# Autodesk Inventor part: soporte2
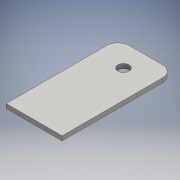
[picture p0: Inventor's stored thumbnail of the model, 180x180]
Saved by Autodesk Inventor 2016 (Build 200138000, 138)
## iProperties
Created: 2016-06
Part Number: soporte2
Material: Genérico
Document SubType Name: Modeling
Designer: adm
Density: 1 g/cm^3
Appearance: Valor por defecto
Author: adm
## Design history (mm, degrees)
sketch "Boceto1"
  geometry: L1 (-25, -50)-(25, -50); L2 (25, -50)-(25, 50); L3 (25, 50)-(-25, 50); L4 (-25, 50)-(-25, -50); L5 (-25, -50)-(25, 50); L6 (25, -50)-(-25, 50); C1 r 5 at (0, 30); 2 further points
  constraints: 12 end point, 2 midpoint, 2 parallel, 1 centre point, 1 coincident, 1 horizontal, 1 perpendicular
  dimensions: "d0" = 50 distance of L3.end L2.end; "d1" = 100 distance of L2.end L1.end; "d2" = 20 distance from line of point (0, 30) L3; "d3" = 10 diameter of C1
extrude "Extrusión1" new body sketch "Boceto1" distance "d4" = 4; taper "d5" = 0 deg
fillet "Empalme1" dims "d6" = 10
node "Sólido1"
